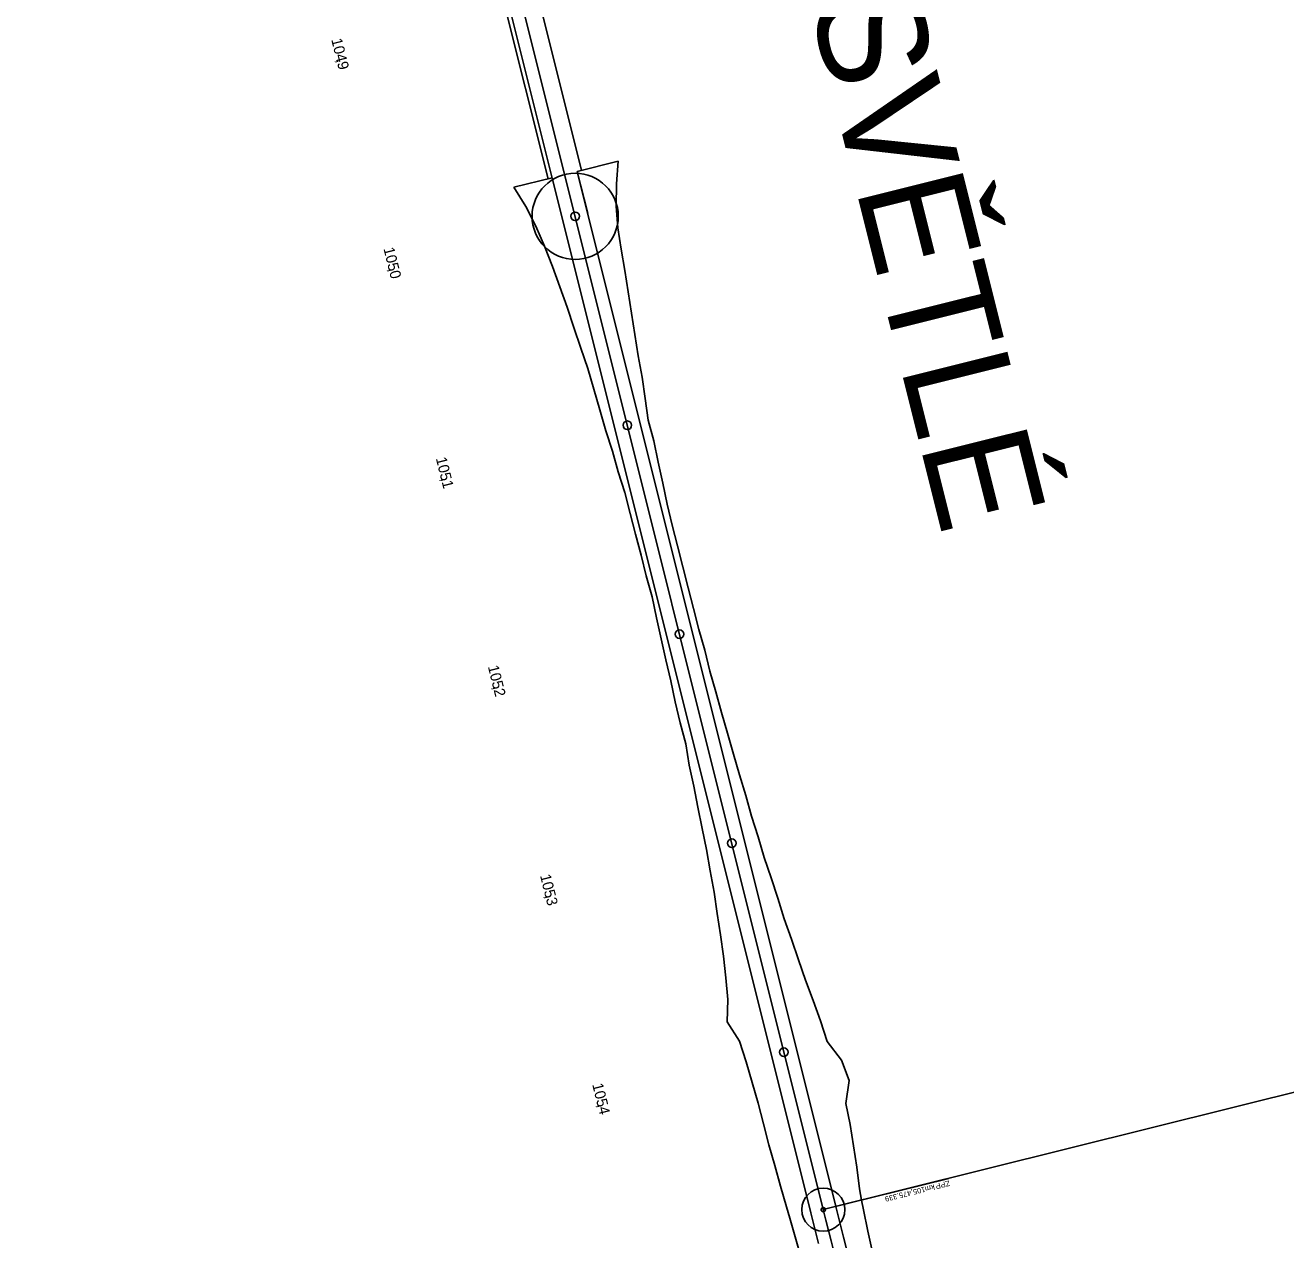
# Model space of a CAD drawing. Extents: x -678487 to -674601, y -1104811 to -1093295.
# Drawn here: x -676082 to -675496, y -1102037 to -1101474 of the extents above; entities that cross this region are included whole.
import ezdxf

# ---------------------------------------------------------------- set-up
doc = ezdxf.new("R2010")
doc.units = 0
for name, color, linetype in [('00_MiNGO', 7, 'Continuous'), ('SOxxxxxx_Koleje_dopravna_Popis', 7, 'Continuous'), ('SOxxxxxx_Koleje_hlavní_body_Popis', 7, 'Continuous'), ('SOxxxxxx_Koleje_hlavní_body_Popis10', 7, 'Continuous'), ('SOxxxxxx_Osa_bod_P', 7, 'Continuous'), ('SOxxxxxx_Staničení_Popis', 7, 'Continuous'), ('SOxxxxxx_Staničení_Popis10', 7, 'Continuous'), ('SOxxxxxx_ŽSp_hrana', 7, 'Continuous'), ('SOxxxxxx_ŽSp_násyp_hrana', 7, 'Continuous'), ('SOxxxxxx_ŽSp_násyp_plocha', 7, 'Continuous')]:
    doc.layers.add(name, color=color, linetype=linetype)

msp = doc.modelspace()

# ---------------------------------------------------------------- linework, layer by layer
at = {"layer": '00_MiNGO'}
for p, q in [((-675838.85, -1101544.83), (-675863.08, -1101447.81)), ((-675838.85, -1101544.83), (-675863.08, -1101447.81)), ((-675823.33, -1101540.95), (-675847.56, -1101443.93)), ((-675823.33, -1101540.95), (-675847.56, -1101443.93))]:
    msp.add_line(p, q, dxfattribs=at)
at = {"layer": 'SOxxxxxx_Koleje_hlavní_body_Popis'}
for q in [(-675652.87, -1102008.94), (-675711.08, -1102023.47)]:
    msp.add_line((-675711.08, -1102023.47), q, dxfattribs=at)
msp.add_circle((-675711.08, -1102023.47), 1, dxfattribs=at)
at = {"layer": 'SOxxxxxx_Koleje_hlavní_body_Popis10'}
for q in [(-675128.96, -1101878.11), (-675711.08, -1102023.47)]:
    msp.add_line((-675711.08, -1102023.47), q, dxfattribs=at)
msp.add_circle((-675711.08, -1102023.47), 10, dxfattribs=at)
at = {"layer": 'SOxxxxxx_Osa_bod_P'}
msp.add_line((-676081.52, -1100540.04), (-675711.08, -1102023.47), dxfattribs=at)
msp.add_open_spline([(-675711.08, -1102023.47), (-675704.64, -1102049.27), (-675691.77, -1102100.86), (-675672.21, -1102178.19), (-675652.24, -1102255.41), (-675638.47, -1102306.77), (-675631.44, -1102332.41)], degree=3, dxfattribs=at)
at = {"layer": 'SOxxxxxx_Staničení_Popis'}
for p, q in [((-675826.25, -1101562.29), (-675826.25, -1101562.29)), ((-675802.02, -1101659.32), (-675802.02, -1101659.32)), ((-675777.79, -1101756.34), (-675777.79, -1101756.34)), ((-675753.56, -1101853.36), (-675753.56, -1101853.36)), ((-675729.34, -1101950.38), (-675729.34, -1101950.38))]:
    msp.add_line(p, q, dxfattribs=at)
for centre in [(-675826.25, -1101562.29), (-675802.02, -1101659.32), (-675777.79, -1101756.34), (-675753.56, -1101853.36), (-675729.34, -1101950.38)]:
    msp.add_circle(centre, 2, dxfattribs=at)
at = {"layer": 'SOxxxxxx_Staničení_Popis10'}
msp.add_line((-675826.25, -1101562.29), (-675826.25, -1101562.29), dxfattribs=at)
msp.add_circle((-675826.25, -1101562.29), 20, dxfattribs=at)
at = {"layer": 'SOxxxxxx_ŽSp_hrana'}
for p, q in [((-675989.56, -1100933.12), (-675832.08, -1101563.75)), ((-675825.26, -1101541.43), (-675820.42, -1101560.84))]:
    msp.add_line(p, q, dxfattribs=at)
for points in [[(-675825.26, -1101541.43), (-675705.25, -1102022.02), (-675701.7, -1102036.24), (-675699.28, -1102045.94)], [(-675836.92, -1101544.35), (-675716.91, -1102024.93), (-675713.36, -1102039.15)]]:
    msp.add_lwpolyline(points, dxfattribs=at)
at = {"layer": 'SOxxxxxx_ŽSp_násyp_hrana'}
for p, q in [((-675806.26, -1101536.69), (-675807.01, -1101547.18)), ((-675806.26, -1101536.69), (-675807.01, -1101547.18)), ((-675854.66, -1101548.78), (-675849.18, -1101557.71)), ((-675854.66, -1101548.78), (-675849.18, -1101557.71)), ((-675807.01, -1101547.18), (-675807.17, -1101557.53)), ((-675807.01, -1101547.18), (-675807.17, -1101557.53)), ((-675849.18, -1101557.71), (-675844.53, -1101566.86)), ((-675849.18, -1101557.71), (-675844.53, -1101566.86)), ((-675807.17, -1101557.53), (-675806.38, -1101567.64)), ((-675844.53, -1101566.86), (-675840.54, -1101576.17)), ((-675806.38, -1101567.64), (-675804.86, -1101577.57)), ((-675840.54, -1101576.17), (-675836.74, -1101585.53)), ((-675804.86, -1101577.57), (-675803.13, -1101587.44)), ((-675836.74, -1101585.53), (-675833.29, -1101594.97)), ((-675803.13, -1101587.44), (-675801.62, -1101597.37)), ((-675833.29, -1101594.97), (-675829.97, -1101604.45)), ((-675801.62, -1101597.37), (-675800.15, -1101607.31)), ((-675829.97, -1101604.45), (-675826.8, -1101613.97)), ((-675800.15, -1101607.31), (-675798.5, -1101617.21)), ((-675826.8, -1101613.97), (-675823.63, -1101623.48)), ((-675798.5, -1101617.21), (-675797.01, -1101627.14)), ((-675823.63, -1101623.48), (-675820.34, -1101632.97)), ((-675797.01, -1101627.14), (-675795.1, -1101636.97)), ((-675820.34, -1101632.97), (-675817.55, -1101642.58)), ((-675817.55, -1101642.58), (-675814.86, -1101652.21)), ((-675795.1, -1101636.97), (-675793.69, -1101646.93)), ((-675793.69, -1101646.93), (-675792.32, -1101656.89)), ((-675814.86, -1101652.21), (-675812.01, -1101661.81)), ((-675792.32, -1101656.89), (-675789.8, -1101666.57)), ((-675812.01, -1101661.81), (-675808.99, -1101671.36)), ((-675808.99, -1101671.36), (-675806.23, -1101680.98)), ((-675789.8, -1101666.57), (-675787.76, -1101676.37)), ((-675787.76, -1101676.37), (-675785.54, -1101686.12)), ((-675806.23, -1101680.98), (-675803.25, -1101690.54)), ((-675785.54, -1101686.12), (-675783.53, -1101695.93)), ((-675803.25, -1101690.54), (-675800.78, -1101700.23)), ((-675800.78, -1101700.23), (-675798.21, -1101709.9)), ((-675783.53, -1101695.93), (-675781.17, -1101705.64)), ((-675781.17, -1101705.64), (-675778.73, -1101715.34)), ((-675798.21, -1101709.9), (-675795.58, -1101719.55)), ((-675778.73, -1101715.34), (-675776.31, -1101725.05)), ((-675795.58, -1101719.55), (-675793.23, -1101729.27)), ((-675793.23, -1101729.27), (-675790.56, -1101738.91)), ((-675776.31, -1101725.05), (-675773.79, -1101734.72)), ((-675773.79, -1101734.72), (-675771.39, -1101744.43)), ((-675790.56, -1101738.91), (-675788.5, -1101748.7)), ((-675771.39, -1101744.43), (-675768.81, -1101754.09)), ((-675788.5, -1101748.7), (-675786.35, -1101758.47)), ((-675786.35, -1101758.47), (-675784.11, -1101768.22)), ((-675768.81, -1101754.09), (-675766.07, -1101763.72)), ((-675766.07, -1101763.72), (-675763.81, -1101773.46)), ((-675784.11, -1101768.22), (-675781.91, -1101777.98)), ((-675763.81, -1101773.46), (-675760.93, -1101783.05)), ((-675781.91, -1101777.98), (-675779.78, -1101787.75)), ((-675779.78, -1101787.75), (-675777.53, -1101797.5)), ((-675760.93, -1101783.05), (-675758.27, -1101792.69)), ((-675758.27, -1101792.69), (-675755.53, -1101802.31)), ((-675777.53, -1101797.5), (-675774.89, -1101807.15)), ((-675755.53, -1101802.31), (-675752.76, -1101811.93)), ((-675774.89, -1101807.15), (-675773.34, -1101817.07)), ((-675752.76, -1101811.93), (-675749.98, -1101821.54)), ((-675773.34, -1101817.07), (-675771.19, -1101826.84)), ((-675749.98, -1101821.54), (-675747.09, -1101831.12)), ((-675771.19, -1101826.84), (-675769.26, -1101836.66)), ((-675747.09, -1101831.12), (-675744.36, -1101840.75)), ((-675769.26, -1101836.66), (-675767.32, -1101846.48)), ((-675744.36, -1101840.75), (-675741.37, -1101850.31)), ((-675767.32, -1101846.48), (-675765.24, -1101856.27)), ((-675741.37, -1101850.31), (-675738.49, -1101859.9)), ((-675765.24, -1101856.27), (-675763.59, -1101866.17)), ((-675738.49, -1101859.9), (-675735.28, -1101869.4)), ((-675763.59, -1101866.17), (-675761.76, -1101876.02)), ((-675735.28, -1101869.4), (-675732.15, -1101878.93)), ((-675761.76, -1101876.02), (-675760.32, -1101885.97)), ((-675732.15, -1101878.93), (-675729.21, -1101888.5)), ((-675760.32, -1101885.97), (-675758.77, -1101895.89)), ((-675729.21, -1101888.5), (-675725.82, -1101897.96)), ((-675758.77, -1101895.89), (-675757.36, -1101905.84)), ((-675725.82, -1101897.96), (-675722.62, -1101907.47)), ((-675757.36, -1101905.84), (-675756.35, -1101915.89)), ((-675722.62, -1101907.47), (-675719.29, -1101916.95)), ((-675756.35, -1101915.89), (-675755.39, -1101925.96)), ((-675719.29, -1101916.95), (-675715.78, -1101926.38)), ((-675755.39, -1101925.96), (-675755.68, -1101936.34)), ((-675715.78, -1101926.38), (-675712.42, -1101935.85)), ((-675755.68, -1101936.34), (-675749.92, -1101945.21)), ((-675712.42, -1101935.85), (-675709.23, -1101945.36)), ((-675749.92, -1101945.21), (-675746.92, -1101954.77)), ((-675709.23, -1101945.36), (-675702.63, -1101954.02)), ((-675746.92, -1101954.77), (-675744.14, -1101964.38)), ((-675702.63, -1101954.02), (-675699.05, -1101963.43)), ((-675744.14, -1101964.38), (-675741.33, -1101973.99)), ((-675699.05, -1101963.43), (-675700.68, -1101974.14)), ((-675741.33, -1101973.99), (-675738.86, -1101983.68)), ((-675700.68, -1101974.14), (-675698.61, -1101983.93)), ((-675738.86, -1101983.68), (-675736.34, -1101993.35)), ((-675698.61, -1101983.93), (-675697.1, -1101993.86)), ((-675736.34, -1101993.35), (-675733.57, -1102002.97)), ((-675697.1, -1101993.86), (-675695.57, -1102003.79)), ((-675733.57, -1102002.97), (-675730.91, -1102012.61)), ((-675695.57, -1102003.79), (-675694.19, -1102013.75)), ((-675730.91, -1102012.61), (-675728.16, -1102022.23)), ((-675694.19, -1102013.75), (-675693.34, -1102019.04)), ((-675728.16, -1102022.23), (-675726.6, -1102027.35)), ((-675693.34, -1102019.04), (-675692.41, -1102023.61)), ((-675726.6, -1102027.35), (-675725.29, -1102031.82)), ((-675692.41, -1102023.61), (-675690.45, -1102033.43)), ((-675725.29, -1102031.82), (-675722.55, -1102041.45)), ((-675690.45, -1102033.43), (-675688.17, -1102043.17))]:
    msp.add_line(p, q, dxfattribs=at)
at = {"layer": 'SOxxxxxx_ŽSp_násyp_plocha'}
for p, q in [((-675825.26, -1101541.43), (-675806.26, -1101536.69)), ((-675806.26, -1101536.69), (-675807.01, -1101547.18)), ((-675825.26, -1101541.43), (-675820.42, -1101560.84)), ((-675854.66, -1101548.78), (-675836.92, -1101544.35)), ((-675854.66, -1101548.78), (-675849.18, -1101557.71)), ((-675836.92, -1101544.35), (-675832.08, -1101563.75)), ((-675807.01, -1101547.18), (-675807.17, -1101557.53)), ((-675849.18, -1101557.71), (-675844.53, -1101566.86))]:
    msp.add_line(p, q, dxfattribs=at)
for points in [[(-675806.26, -1101536.69), (-675807.01, -1101547.18), (-675807.17, -1101557.53), (-675806.38, -1101567.64), (-675804.86, -1101577.57), (-675803.13, -1101587.44), (-675801.62, -1101597.37), (-675800.15, -1101607.31), (-675798.5, -1101617.21), (-675797.01, -1101627.14), (-675795.1, -1101636.97), (-675793.69, -1101646.93), (-675792.32, -1101656.89), (-675789.8, -1101666.57), (-675787.76, -1101676.37), (-675785.54, -1101686.12), (-675783.53, -1101695.93), (-675781.17, -1101705.64), (-675778.73, -1101715.34), (-675776.31, -1101725.05), (-675773.79, -1101734.72), (-675771.39, -1101744.43), (-675768.81, -1101754.09), (-675766.07, -1101763.72), (-675763.81, -1101773.46), (-675760.93, -1101783.05), (-675758.27, -1101792.69), (-675755.53, -1101802.31), (-675752.76, -1101811.93), (-675749.98, -1101821.54), (-675747.09, -1101831.12), (-675744.36, -1101840.75), (-675741.37, -1101850.31), (-675738.49, -1101859.9), (-675735.28, -1101869.4), (-675732.15, -1101878.93), (-675729.21, -1101888.5), (-675725.82, -1101897.96), (-675722.62, -1101907.47), (-675719.29, -1101916.95), (-675715.78, -1101926.38), (-675712.42, -1101935.85), (-675709.23, -1101945.36), (-675702.63, -1101954.02), (-675699.05, -1101963.43), (-675700.68, -1101974.14), (-675698.61, -1101983.93), (-675697.1, -1101993.86), (-675695.57, -1102003.79), (-675694.19, -1102013.75), (-675693.34, -1102019.04), (-675692.41, -1102023.61), (-675690.45, -1102033.43), (-675688.17, -1102043.17)], [(-675699.28, -1102045.94), (-675701.7, -1102036.24), (-675705.25, -1102022.02), (-675825.26, -1101541.43)], [(-675722.55, -1102041.45), (-675725.29, -1102031.82), (-675726.6, -1102027.35), (-675728.16, -1102022.23), (-675730.91, -1102012.61), (-675733.57, -1102002.97), (-675736.34, -1101993.35), (-675738.86, -1101983.68), (-675741.33, -1101973.99), (-675744.14, -1101964.38), (-675746.92, -1101954.77), (-675749.92, -1101945.21), (-675755.68, -1101936.34), (-675755.39, -1101925.96), (-675756.35, -1101915.89), (-675757.36, -1101905.84), (-675758.77, -1101895.89), (-675760.32, -1101885.97), (-675761.76, -1101876.02), (-675763.59, -1101866.17), (-675765.24, -1101856.27), (-675767.32, -1101846.48), (-675769.26, -1101836.66), (-675771.19, -1101826.84), (-675773.34, -1101817.07), (-675774.89, -1101807.15), (-675777.53, -1101797.5), (-675779.78, -1101787.75), (-675781.91, -1101777.98), (-675784.11, -1101768.22), (-675786.35, -1101758.47), (-675788.5, -1101748.7), (-675790.56, -1101738.91), (-675793.23, -1101729.27), (-675795.58, -1101719.55), (-675798.21, -1101709.9), (-675800.78, -1101700.23), (-675803.25, -1101690.54), (-675806.23, -1101680.98), (-675808.99, -1101671.36), (-675812.01, -1101661.81), (-675814.86, -1101652.21), (-675817.55, -1101642.58), (-675820.34, -1101632.97), (-675823.63, -1101623.48), (-675826.8, -1101613.97), (-675829.97, -1101604.45), (-675833.29, -1101594.97), (-675836.74, -1101585.53), (-675840.54, -1101576.17), (-675844.53, -1101566.86), (-675849.18, -1101557.71), (-675854.66, -1101548.78)], [(-675836.92, -1101544.35), (-675716.91, -1102024.93), (-675713.36, -1102039.15)]]:
    msp.add_lwpolyline(points, dxfattribs=at)

# ---------------------------------------------------------------- texts
at = {"layer": 'SOxxxxxx_Koleje_dopravna_Popis'}
msp.add_text('ODB NOVÁ VES U SVĚTLÉ', height=50, rotation=284.02791, dxfattribs=at).set_placement((-675860.95, -1100889.39))
at = {"layer": 'SOxxxxxx_Koleje_hlavní_body_Popis'}
for s, p in [('P', (-675656.95, -1102010.99)), ('ZP', (-675652.63, -1102009.91)), ('105,475.339', (-675664.06, -1102012.76)), (' km ', (-675658.8, -1102011.45))]:
    msp.add_text(s, height=2.5, rotation=194.02095, dxfattribs=at).set_placement(p)
at = {"layer": 'SOxxxxxx_Staničení_Popis'}
for s, p in [('104', (-675939.5, -1101480.25)), (',', (-675937.18, -1101489.52)), ('9', (-675936.8, -1101491.07)), ('105', (-675915.27, -1101577.28)), (',', (-675912.95, -1101586.55)), ('0', (-675912.57, -1101588.1)), ('105', (-675890.95, -1101674.68)), (',', (-675888.63, -1101683.95)), ('1', (-675888.24, -1101685.5)), ('105', (-675866.81, -1101771.33)), (',', (-675864.5, -1101780.61)), ('2', (-675864.11, -1101782.15)), ('105', (-675842.59, -1101868.34)), (',', (-675840.27, -1101877.61)), ('3', (-675839.89, -1101879.16)), ('105', (-675818.36, -1101965.36)), (',', (-675816.04, -1101974.64)), ('4', (-675815.66, -1101976.18))]:
    msp.add_text(s, height=5, rotation=284.02095, dxfattribs=at).set_placement(p)

doc.saveas('drawing.dxf')
